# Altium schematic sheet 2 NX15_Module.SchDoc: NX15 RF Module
size A4; SheetNumber: 1; SheetTotal: 1
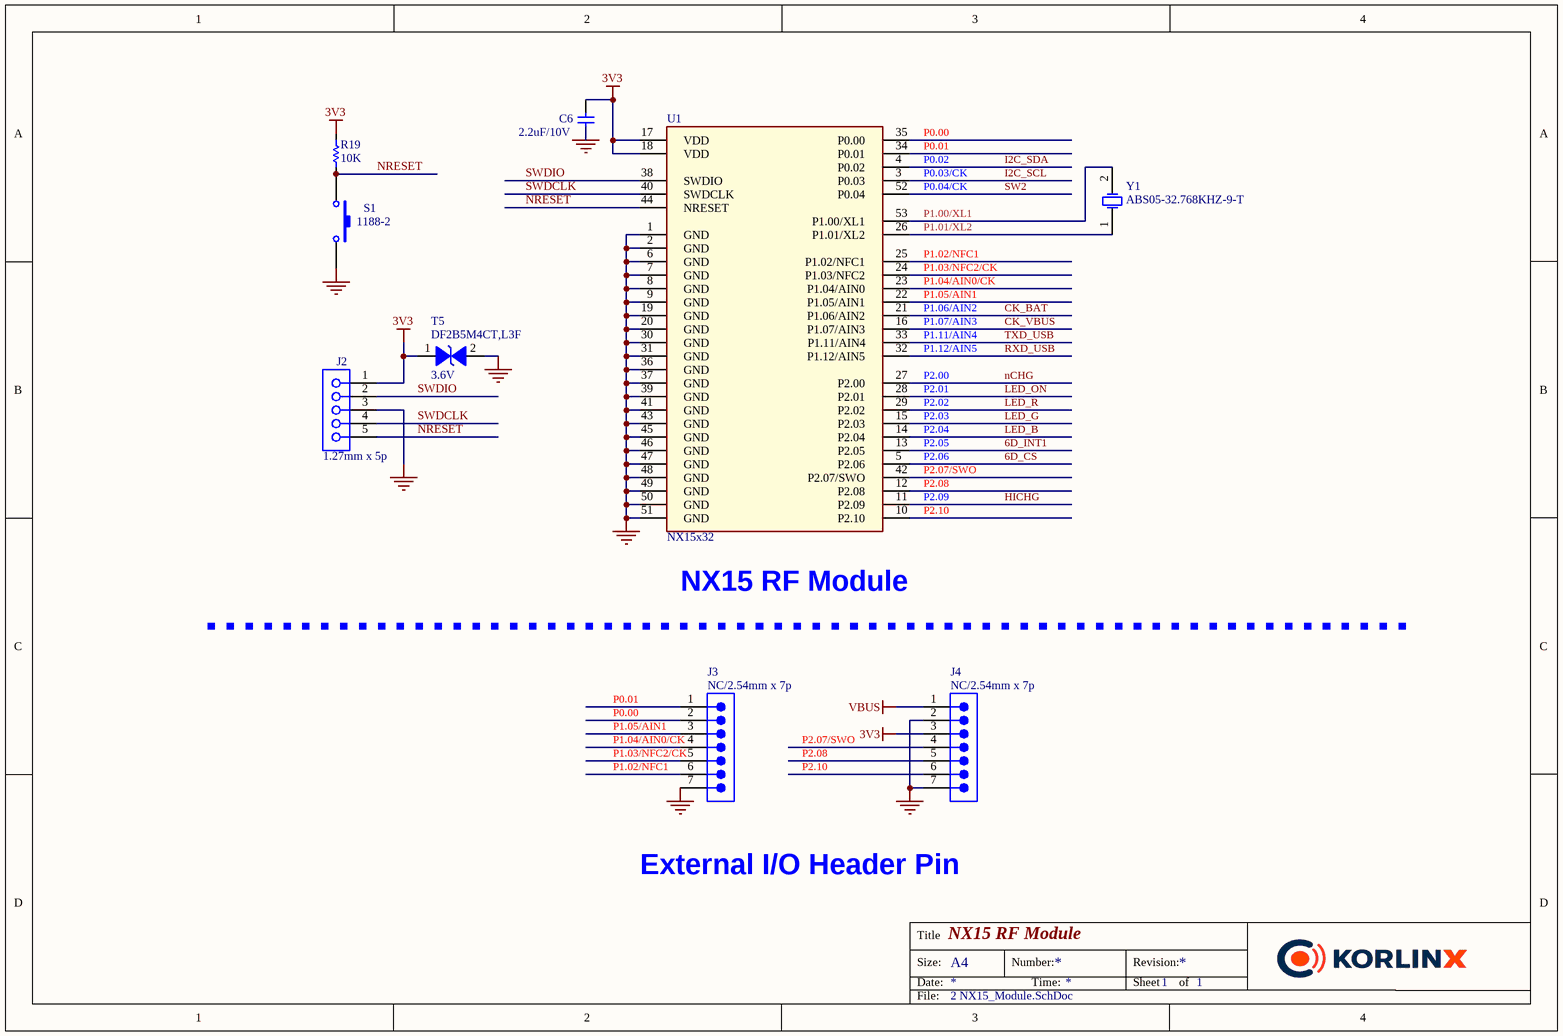
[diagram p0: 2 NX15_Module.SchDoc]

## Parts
C6  2.2uF/10V  [CAP 0402/1005]
J2  1.27mm x 5p  [PIN HEADER 1X5 TH 1.27mm]
J3  NC/2.54mm x 7p  [61300711121]
J4  NC/2.54mm x 7p  [61300711121]
R19  10K  [RES 0402/1005]
S1  1188-2  [SW TACT NANOT-AS]
T5  DF2B5M4CT,L3F  Working Voltage: 3.6V  [DFN1006-2L]
U1  NX15x32  [NX15E32]
Y1  ABS05-32.768KHZ-9-T  [XTAL 1610]

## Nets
3V3: C6.2 J2.1 J4.3 R19.1 T5.1(A) U1.17(VDD) U1.18(VDD)
GND: C6.1 J2.3 J3.7 J4.2 J4.7 S1.2 T5.2(K) U1.1(GND) U1.2(GND) U1.6(GND) U1.7(GND) U1.8(GND) U1.9(GND) U1.19(GND) U1.20(GND) U1.30(GND) U1.31(GND) U1.36(GND) U1.37(GND) U1.39(GND) U1.41(GND) U1.43(GND) U1.45(GND) U1.46(GND) U1.47(GND) U1.48(GND) U1.49(GND) U1.50(GND) U1.51(GND)
VBUS: J4.1
6D_CS: U1.5(P2.06)
6D_INT1: U1.13(P2.05)
CK_BAT: U1.21(P1.06/AIN2)
CK_VBUS: U1.16(P1.07/AIN3)
HICHG: U1.11(P2.09)
I2C_SCL: U1.3(P0.03)
I2C_SDA: U1.4(P0.02)
LED_B: U1.14(P2.04)
LED_G: U1.15(P2.03)
LED_ON: U1.28(P2.01)
LED_R: U1.29(P2.02)
nCHG: U1.27(P2.00)
NRESET: J2.5 R19.2 S1.1 U1.44(NRESET)
P0.00: J3.2 U1.35(P0.00)
P0.01: J3.1 U1.34(P0.01)
P1.00/XL1: U1.53(P1.00/XL1) Y1.2(OSC2)
P1.01/XL2: U1.26(P1.01/XL2) Y1.1(OSC1)
P1.02/NFC1: J3.6 U1.25(P1.02/NFC1)
P1.03/NFC2/CK: J3.5 U1.24(P1.03/NFC2)
P1.04/AIN0/CK: J3.4 U1.23(P1.04/AIN0)
P1.05/AIN1: J3.3 U1.22(P1.05/AIN1)
P2.07/SWO: J4.4 U1.42(P2.07/SWO)
P2.08: J4.5 U1.12(P2.08)
P2.10: J4.6 U1.10(P2.10)
RXD_USB: U1.32(P1.12/AIN5)
SW2: U1.52(P0.04)
SWDCLK: J2.4 U1.40(SWDCLK)
SWDIO: J2.2 U1.38(SWDIO)
TXD_USB: U1.33(P1.11/AIN4)

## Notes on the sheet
- (near U1) P0.02
- (near U1) P0.03/CK
- (near U1) P0.04/CK
- (near U1) P1.06/AIN2
- (near U1) P1.07/AIN3
- (near U1) P1.11/AIN4
- (near U1) P2.00
- (near U1) P1.12/AIN5
- (near U1) P2.01
- (near U1) P2.02
- (near U1) P2.03
- (near U1) P2.04
- (near U1) P2.05
- (near U1) P2.09
- (near U1) P2.06
- (near U1) NX15 RF Module
- External I/O Header Pin

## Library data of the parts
C6 = Cap: Capacitor MLCC
J2 = 61300515721: Pin Header; Contact Resistance: 20mOhm; Gender: Socket Header; Pitch: 2.54mm; Rated Current: 3A; Working Voltage: 250V; Withstanding Voltage: 500V
J3 J4 = 61300711121: WR-PHD Pin Header, THT, Vertical, pitch 2.54mm, 1 Row, 7P; Manufacturer: Wurth Elektronik; Contact Resistance: 20mOhm; Rated Current: 3A; Working Voltage: 250V; Withstanding Voltage: 500V
R19 = Res1_1: Resistor
S1 = SW-PB: Switch INSUNG-TECHWIN
T5 = Diode TVS: TVS Diode, Bidirectional, 3.6V, 0.3pF(max), SOD-882-2
U1 = NX15x32 / Ver-260811: RF Module
Y1 = XTAL: Crystals 32.768 KHZ 9.0PF -40+85C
